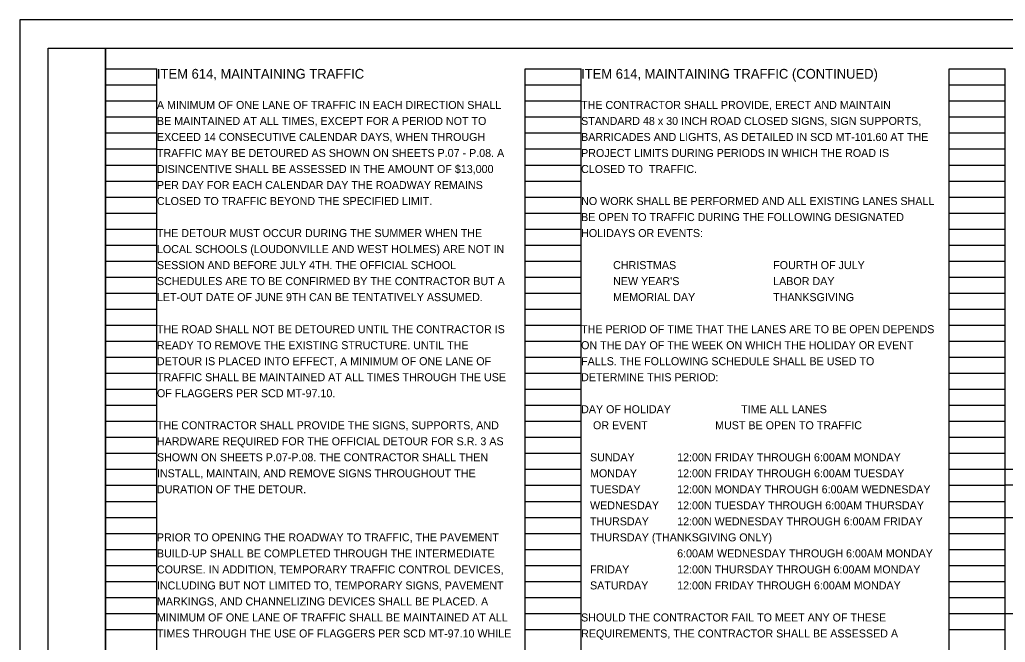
# Model space of a CAD drawing. Extents: x -32.3 to 34, y 0 to 22.
# Drawn here: x 0 to 17.24, y 11.12 to 22 of the extents above; entities that cross this region are included whole.
import ezdxf

# ---------------------------------------------------------------- set-up
doc = ezdxf.new("R2010")
doc.units = 0
for name, color, linetype in [('SH_Border', 7, 'Continuous'), ('SH_Cut_Line', 7, 'Continuous'), ('SH_Data', 7, 'Continuous'), ('SH_Text', 7, 'Continuous')]:
    doc.layers.add(name, color=color, linetype=linetype)

msp = doc.modelspace()

# ---------------------------------------------------------------- linework, layer by layer
at = {"layer": 'SH_Border'}
for points in [[(0.5, 21.5), (1.5, 21.5), (1.5, 0.5), (0.5, 0.5)], [(1.5, 21.5), (33.5, 21.5), (33.5, 0.5), (1.5, 0.5)]]:
    msp.add_lwpolyline(points, close=True, dxfattribs=at)
at = {"layer": 'SH_Cut_Line'}
msp.add_lwpolyline([(0, 0), (34, 0), (34, 22), (0, 22)], close=True, dxfattribs=at)
at = {"layer": 'SH_Data'}
for p, q in [((1.5, 0.98), (1.5, 21.14)), ((1.5, 21.14), (2.4, 21.14)), ((2.4, 0.98), (2.4, 21.14)), ((8.84, 0.98), (8.84, 21.14)), ((8.84, 21.14), (9.82, 21.14)), ((9.82, 0.98), (9.82, 21.14)), ((16.26, 0.98), (16.26, 21.14)), ((16.26, 21.14), (17.24, 21.14)), ((17.24, 0.98), (17.24, 21.14)), ((1.5, 20.86), (2.4, 20.86)), ((8.84, 20.86), (9.82, 20.86)), ((16.26, 20.86), (17.24, 20.86)), ((1.5, 20.58), (2.4, 20.58)), ((8.84, 20.58), (9.82, 20.58)), ((16.26, 20.58), (17.24, 20.58)), ((1.5, 20.3), (2.4, 20.3)), ((8.84, 20.3), (9.82, 20.3)), ((16.26, 20.3), (17.24, 20.3)), ((1.5, 20.02), (2.4, 20.02)), ((8.84, 20.02), (9.82, 20.02)), ((16.26, 20.02), (17.24, 20.02)), ((1.5, 19.74), (2.4, 19.74)), ((8.84, 19.74), (9.82, 19.74)), ((16.26, 19.74), (17.24, 19.74)), ((1.5, 19.46), (2.4, 19.46)), ((8.84, 19.46), (9.82, 19.46)), ((16.26, 19.46), (17.24, 19.46)), ((1.5, 19.18), (2.4, 19.18)), ((8.84, 19.18), (9.82, 19.18)), ((16.26, 19.18), (17.24, 19.18)), ((1.5, 18.9), (2.4, 18.9)), ((8.84, 18.9), (9.82, 18.9)), ((16.26, 18.9), (17.24, 18.9)), ((1.5, 18.62), (2.4, 18.62)), ((8.84, 18.62), (9.82, 18.62)), ((16.26, 18.62), (17.24, 18.62)), ((1.5, 18.34), (2.4, 18.34)), ((8.84, 18.34), (9.82, 18.34)), ((16.26, 18.34), (17.24, 18.34)), ((1.5, 18.06), (2.4, 18.06)), ((8.84, 18.06), (9.82, 18.06)), ((16.26, 18.06), (17.24, 18.06)), ((1.5, 17.78), (2.4, 17.78)), ((8.84, 17.78), (9.82, 17.78)), ((16.26, 17.78), (17.24, 17.78)), ((1.5, 17.5), (2.4, 17.5)), ((8.84, 17.5), (9.82, 17.5)), ((16.26, 17.5), (17.24, 17.5)), ((1.5, 17.22), (2.4, 17.22)), ((8.84, 17.22), (9.82, 17.22)), ((16.26, 17.22), (17.24, 17.22)), ((1.5, 16.94), (2.4, 16.94)), ((8.84, 16.94), (9.82, 16.94)), ((16.26, 16.94), (17.24, 16.94)), ((1.5, 16.66), (2.4, 16.66)), ((8.84, 16.66), (9.82, 16.66)), ((16.26, 16.66), (17.24, 16.66)), ((1.5, 16.38), (2.4, 16.38)), ((8.84, 16.38), (9.82, 16.38)), ((16.26, 16.38), (17.24, 16.38)), ((1.5, 16.1), (2.4, 16.1)), ((8.84, 16.1), (9.82, 16.1)), ((16.26, 16.1), (17.24, 16.1)), ((1.5, 15.82), (2.4, 15.82)), ((8.84, 15.82), (9.82, 15.82)), ((16.26, 15.82), (17.24, 15.82)), ((1.5, 15.54), (2.4, 15.54)), ((8.84, 15.54), (9.82, 15.54)), ((16.26, 15.54), (17.24, 15.54)), ((1.5, 15.26), (2.4, 15.26)), ((8.84, 15.26), (9.82, 15.26)), ((16.26, 15.26), (17.24, 15.26)), ((1.5, 14.98), (2.4, 14.98)), ((8.84, 14.98), (9.82, 14.98)), ((16.26, 14.98), (17.24, 14.98)), ((1.5, 14.7), (2.4, 14.7)), ((8.84, 14.7), (9.82, 14.7)), ((16.26, 14.7), (17.24, 14.7)), ((1.5, 14.42), (2.4, 14.42)), ((8.84, 14.42), (9.82, 14.42)), ((16.26, 14.42), (17.24, 14.42)), ((1.5, 14.14), (2.4, 14.14)), ((8.84, 14.14), (9.82, 14.14)), ((16.26, 14.14), (17.24, 14.14)), ((1.5, 13.86), (2.4, 13.86)), ((8.84, 13.86), (9.82, 13.86)), ((16.26, 13.86), (17.24, 13.86)), ((1.5, 13.58), (2.4, 13.58)), ((8.84, 13.58), (9.82, 13.58)), ((16.26, 13.58), (17.24, 13.58)), ((1.5, 13.3), (2.4, 13.3)), ((8.84, 13.3), (9.82, 13.3)), ((16.26, 13.3), (17.24, 13.3)), ((1.5, 13.02), (2.4, 13.02)), ((8.84, 13.02), (9.82, 13.02)), ((16.26, 13.02), (17.24, 13.02)), ((1.5, 12.74), (2.4, 12.74)), ((8.84, 12.74), (9.82, 12.74)), ((16.26, 12.74), (17.24, 12.74)), ((1.5, 12.46), (2.4, 12.46)), ((8.84, 12.46), (9.82, 12.46)), ((16.26, 12.46), (17.24, 12.46)), ((1.5, 12.18), (2.4, 12.18)), ((8.84, 12.18), (9.82, 12.18)), ((16.26, 12.18), (17.24, 12.18)), ((1.5, 11.9), (2.4, 11.9)), ((8.84, 11.9), (9.82, 11.9)), ((16.26, 11.9), (17.24, 11.9)), ((1.5, 11.62), (2.4, 11.62)), ((8.84, 11.62), (9.82, 11.62)), ((16.26, 11.62), (17.24, 11.62)), ((1.5, 11.34), (2.4, 11.34)), ((8.84, 11.34), (9.82, 11.34)), ((16.26, 11.34), (17.24, 11.34))]:
    msp.add_line(p, q, dxfattribs=at)
at = {"layer": 'SH_Text'}
for p, q in [((17.24, 13.3), (23.68, 13.3)), ((17.24, 11.62), (23.68, 11.62))]:
    msp.add_line(p, q, dxfattribs=at)
msp.add_lwpolyline([(17.24, 14.14), (23.68, 14.14), (23.68, 13.86), (17.24, 13.86)], close=True, dxfattribs=at)

# ---------------------------------------------------------------- texts
for s, height, p in [('ITEM 614, MAINTAINING TRAFFIC', 0.17, (2.4, 20.97)), ('ITEM 614, MAINTAINING TRAFFIC (CONTINUED)', 0.17, (9.82, 20.97)), ('A MINIMUM OF ONE LANE OF TRAFFIC IN EACH DIRECTION SHALL ', 0.14, (2.4, 20.44)), ('THE CONTRACTOR SHALL PROVIDE, ERECT AND MAINTAIN ', 0.14, (9.82, 20.44)), ('BE MAINTAINED AT ALL TIMES, EXCEPT FOR A PERIOD NOT TO ', 0.14, (2.4, 20.16)), ('STANDARD 48 x 30 INCH ROAD CLOSED SIGNS, SIGN SUPPORTS, ', 0.14, (9.82, 20.16)), ('EXCEED 14 CONSECUTIVE CALENDAR DAYS, WHEN THROUGH ', 0.14, (2.4, 19.88)), ('BARRICADES AND LIGHTS, AS DETAILED IN SCD MT-101.60 AT THE ', 0.14, (9.82, 19.88)), ('TRAFFIC MAY BE DETOURED AS SHOWN ON SHEETS P.07 - P.08. A ', 0.14, (2.4, 19.6)), ('PROJECT LIMITS DURING PERIODS IN WHICH THE ROAD IS ', 0.14, (9.82, 19.6)), ('DISINCENTIVE SHALL BE ASSESSED IN THE AMOUNT OF $13,000 ', 0.14, (2.4, 19.32)), ('CLOSED TO  TRAFFIC.', 0.14, (9.82, 19.32)), ('PER DAY FOR EACH CALENDAR DAY THE ROADWAY REMAINS ', 0.14, (2.4, 19.04)), ('CLOSED TO TRAFFIC BEYOND THE SPECIFIED LIMIT.', 0.14, (2.4, 18.76)), ('NO WORK SHALL BE PERFORMED AND ALL EXISTING LANES SHALL ', 0.14, (9.82, 18.76)), ('BE OPEN TO TRAFFIC DURING THE FOLLOWING DESIGNATED ', 0.14, (9.82, 18.48)), ('THE DETOUR MUST OCCUR DURING THE SUMMER WHEN THE ', 0.14, (2.4, 18.2)), ('HOLIDAYS OR EVENTS:', 0.14, (9.82, 18.2)), ('LOCAL SCHOOLS (LOUDONVILLE AND WEST HOLMES) ARE NOT IN ', 0.14, (2.4, 17.92)), ('SESSION AND BEFORE JULY 4TH. THE OFFICIAL SCHOOL ', 0.14, (2.4, 17.64)), ('CHRISTMAS', 0.14, (10.38, 17.64)), ('FOURTH OF JULY', 0.14, (13.18, 17.64)), ('SCHEDULES ARE TO BE CONFIRMED BY THE CONTRACTOR BUT A ', 0.14, (2.4, 17.36)), ("NEW YEAR'S", 0.14, (10.38, 17.36)), ('LABOR DAY', 0.14, (13.18, 17.36)), ('LET-OUT DATE OF JUNE 9TH CAN BE TENTATIVELY ASSUMED.', 0.14, (2.4, 17.08)), ('MEMORIAL DAY', 0.14, (10.38, 17.08)), ('THANKSGIVING', 0.14, (13.18, 17.08)), ('THE ROAD SHALL NOT BE DETOURED UNTIL THE CONTRACTOR IS ', 0.14, (2.4, 16.52)), ('THE PERIOD OF TIME THAT THE LANES ARE TO BE OPEN DEPENDS ', 0.14, (9.82, 16.52)), ('READY TO REMOVE THE EXISTING STRUCTURE. UNTIL THE ', 0.14, (2.4, 16.24)), ('ON THE DAY OF THE WEEK ON WHICH THE HOLIDAY OR EVENT ', 0.14, (9.82, 16.24)), ('DETOUR IS PLACED INTO EFFECT, A MINIMUM OF ONE LANE OF ', 0.14, (2.4, 15.96)), ('FALLS. THE FOLLOWING SCHEDULE SHALL BE USED TO ', 0.14, (9.82, 15.96)), ('TRAFFIC SHALL BE MAINTAINED AT ALL TIMES THROUGH THE USE ', 0.14, (2.4, 15.68)), ('DETERMINE THIS PERIOD:', 0.14, (9.82, 15.68)), ('OF FLAGGERS PER SCD MT-97.10.', 0.14, (2.4, 15.4)), ('DAY OF HOLIDAY', 0.14, (9.82, 15.12)), ('TIME ALL LANES', 0.14, (12.62, 15.12)), ('THE CONTRACTOR SHALL PROVIDE THE SIGNS, SUPPORTS, AND ', 0.14, (2.4, 14.84)), ('    OR EVENT      ', 0.14, (9.82, 14.84)), ('  MUST BE OPEN TO TRAFFIC', 0.14, (12.06, 14.84)), ('HARDWARE REQUIRED FOR THE OFFICIAL DETOUR FOR S.R. 3 AS ', 0.14, (2.4, 14.56)), ('SHOWN ON SHEETS P.07-P.08. THE CONTRACTOR SHALL THEN ', 0.14, (2.4, 14.28)), ('   SUNDAY', 0.14, (9.82, 14.28)), ('12:00N FRIDAY THROUGH 6:00AM MONDAY', 0.14, (11.5, 14.28)), ('INSTALL, MAINTAIN, AND REMOVE SIGNS THROUGHOUT THE ', 0.14, (2.4, 14)), ('   MONDAY', 0.14, (9.82, 14)), ('12:00N FRIDAY THROUGH 6:00AM TUESDAY', 0.14, (11.5, 14)), ('DURATION OF THE DETOUR.', 0.14, (2.4, 13.72)), ('   TUESDAY', 0.14, (9.82, 13.72)), ('12:00N MONDAY THROUGH 6:00AM WEDNESDAY', 0.14, (11.5, 13.72)), ('   WEDNESDAY', 0.14, (9.82, 13.44)), ('12:00N TUESDAY THROUGH 6:00AM THURSDAY', 0.14, (11.5, 13.44)), ('   THURSDAY', 0.14, (9.82, 13.16)), ('12:00N WEDNESDAY THROUGH 6:00AM FRIDAY', 0.14, (11.5, 13.16)), ('PRIOR TO OPENING THE ROADWAY TO TRAFFIC, THE PAVEMENT ', 0.14, (2.4, 12.88)), ('   THURSDAY (THANKSGIVING ONLY)', 0.14, (9.82, 12.88)), ('BUILD-UP SHALL BE COMPLETED THROUGH THE INTERMEDIATE ', 0.14, (2.4, 12.6)), ('6:00AM WEDNESDAY THROUGH 6:00AM MONDAY', 0.14, (11.5, 12.6)), ('COURSE. IN ADDITION, TEMPORARY TRAFFIC CONTROL DEVICES, ', 0.14, (2.4, 12.32)), ('   FRIDAY', 0.14, (9.82, 12.32)), ('12:00N THURSDAY THROUGH 6:00AM MONDAY', 0.14, (11.5, 12.32)), ('INCLUDING BUT NOT LIMITED TO, TEMPORARY SIGNS, PAVEMENT ', 0.14, (2.4, 12.04)), ('   SATURDAY', 0.14, (9.82, 12.04)), ('12:00N FRIDAY THROUGH 6:00AM MONDAY', 0.14, (11.5, 12.04)), ('MARKINGS, AND CHANNELIZING DEVICES SHALL BE PLACED. A ', 0.14, (2.4, 11.76)), ('MINIMUM OF ONE LANE OF TRAFFIC SHALL BE MAINTAINED AT ALL ', 0.14, (2.4, 11.48)), ('SHOULD THE CONTRACTOR FAIL TO MEET ANY OF THESE ', 0.14, (9.82, 11.48)), ('TIMES THROUGH THE USE OF FLAGGERS PER SCD MT-97.10 WHILE ', 0.14, (2.4, 11.2)), ('REQUIREMENTS, THE CONTRACTOR SHALL BE ASSESSED A ', 0.14, (9.82, 11.2))]:
    msp.add_text(s, height=height, dxfattribs=at).set_placement(p)

doc.saveas('drawing.dxf')
